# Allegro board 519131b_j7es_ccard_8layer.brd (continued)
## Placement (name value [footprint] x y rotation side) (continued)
J6  FAKRA II  [CONN-ST-FAKRA]  96.52 147.06 180 top
J7  FAKRA II  [CONN-ST-FAKRA]  54.99 146.42 180 top
J8  STX-4235-3/3  [CON_AV6_STX-4235-3-3_S_R_T_26]  6.99 129.02 270 top
J9  STX-4235-3/3  [CON_AV6_STX-4235-3-3_S_R_T_26]  6.99 109.97 270 top
J10  NP-HDR3  [HPH1-3-4025]  54.74 105.27 270 top
J11  2214BR-10G  [CON-2214BR-10G]  199.64 102.22 90 top
J12  STX-4235-3/3  [CON_AV6_STX-4235-3-3_S_R_T_26]  6.99 90.92 270 top
J13  Molex 34826-0124  [MOLEX-34826-0124]  14.86 53.33 270 top
J14  FAN  [CON2-200-250]  165.23 45.33 90 top
J15  MIPI-QSH-030  [QSH-030-01-F]  139.06 42.66 180 top
J16  D4S10E-40MA5-C  [CON_D4S10E]  108.58 6.59 0 top
J17  Phoenix_1868076  [PHOENIX_1868076]  182.25 9.01 0 top
J18  CON_MUSB_20_F  [CON_USB20_472720001_S_R_T_7]  133.84 6.22 0 top
J19  USBMINI_AB  [SAMTEC-MUSB]  16.31 8.75 0 top
J20  mini-pcie  [MOLEX-67910-0002]  89.28 125.97 180 bottom
J21  FX8-120P-SV1-91  [FX8-120P-SV1]  7.9 43.68 270 bottom
L1  NP  [L402-25]  69.6 149.6 270 top
L2  NP  [L402-25]  72.01 149.6 90 top
L3  72nH  [IND603-AISC-25X40]  39.37 138.04 270 top
L4  IHLP2020CZER2R2M01  [IND-IHLP2020]  107.57 137.78 0 top
L5  72nH  [IND603-AISC-25X40]  54.99 137.02 270 top
L6  330nH  [IND603-AISC-25X40]  26.92 134.23 0 top
L7  18nH  [IND603-AISC-25X40]  38.73 133.72 0 top
L8  3.3uH  [IND2-7030D]  169.8 133.72 90 top
L9  3.3uH  [IND2-7030D]  177.42 133.72 90 top
L10  3.3uH  [IND2-7030D]  185.04 133.72 90 top
L11  3.3uH  [IND2-7030D]  192.66 133.72 90 top
L12  62nH  [IND603-AISC-25X40]  48.9 133.59 90 top
L13  1.0uH  [IND0805-40X70]  30.35 133.21 180 top
L14  100nH  [IND603-AISC-25X40]  55.63 132.7 180 top
L15  100nH  [IND603-AISC-25X40]  38.73 131.94 0 top
L16  62nH  [IND603-AISC-25X40]  45.59 131.18 90 top
L17  39nH  [IND603-AISC-25X40]  49.4 130.93 0 top
L18  18nH  [IND603-AISC-25X40]  55.63 130.93 180 top
L19  1.5uH  [IND0805-40X70]  30.48 129.53 270 top
L20  160nH  [IND603-AISC-25X40]  39.37 129.28 270 top
L21  39nH  [IND603-AISC-25X40]  45.09 128.51 180 top
L22  160nH  [IND603-AISC-25X40]  54.99 128.26 270 top
L23  68nH  [IND603-AISC-25X40]  49.4 126.99 0 top
L24  72nH  [IND603-AISC-25X40]  38.61 124.7 0 top
L25  68nH  [IND603-AISC-25X40]  45.09 124.7 180 top
L26  72nH  [IND603-AISC-25X40]  55.75 123.69 180 top
L27  MPZ2012S102A  [L805-35X60]  36.2 118.86 90 top
L28  0.47uH  [IND1008_1-2]  70.99 113.02 180 top
L29  0.47uH  [IND1008_1-2]  82.17 113.02 0 top
L30  1uH  [IND1008_1-2]  69.09 108.96 180 top
L31  MPZ2012S102A  [L805-35X60]  31.75 104.26 90 top
L32  0.47uH  [IND1008_1-2]  124.84 102.99 90 top
L33  1uH  [IND1008_1-2]  138.05 102.99 90 top
L34  0.47uH  [IND1008_1-2]  70.99 99.81 180 top
L35  0.47uH  [IND1008_1-2]  82.17 99.81 0 top
L36  0.47uH  [IND1008_1-2]  124.84 91.81 270 top
L37  1uH  [IND1008_1-2]  138.05 91.81 270 top
L38  1uH  [IND1008_1-2]  128.91 89.91 270 top
L39  2.2uH  [IND_SRP1265A]  171.83 85.33 180 top
L40  120nH  [IND1608-27X40]  32.89 60.06 180 top
L41  AE2002  [CHOKE4-AE2002]  25.78 59.3 0 top
L42  120nH  [IND1608-27X40]  32.89 58.54 180 top
L43  5.6uH - IHLP5050FDER5R6M01  [IND-IHLP5050]  160.91 56 90 top
L44  XFL4012-471MEB, 470nH  [COIL-XLF4012]  151.13 31.99 90 top
L45  DFE252012PD-2R2M  [IND2520-40X80]  44.58 22.6 270 top
L46  3.3uH, 9A  [IND-DFEG10040]  174.62 21.07 180 top
L47  BLM18AG601SN1D  [L603-35X45]  23.5 20.82 180 top
L48  BLM18AG601SN1D  [L603-35X45]  30.91 20.82 0 top
L49  3.3uH, 13A  [IND-DFEH12060]  191.77 20.44 0 top
L50  XAL4020-222MEB  [COIL-XAL40]  152.15 9.39 180 top
L51  MPZ1608S102ATA00  [L603-35X45]  77.98 5.96 90 top
L52  MPZ1608S102ATA00  [L603-35X45]  28.07 5.96 90 top
L53  MPZ1608S102ATA00  [L603-35X45]  44.7 5.96 90 top
L54  MPZ1608S102ATA00  [L603-35X45]  61.34 5.96 90 top
L55  3.3uH  [IND2-7030D]  188.21 133.72 90 bottom
L56  3.3uH  [IND2-7030D]  180.47 133.72 90 bottom
L57  3.3uH  [IND2-7030D]  172.97 133.72 90 bottom
L58  3.3uH  [IND2-7030D]  165.48 133.72 90 bottom
L59  BLM18HE152SN1  [L603-35X45]  86.36 13.2 180 bottom
L60  BLM18HE152SN1  [L603-35X45]  69.72 13.2 180 bottom
L61  BLM18HE152SN1  [L603-35X45]  53.09 13.2 180 bottom
L62  BLM18HE152SN1  [L603-35X45]  36.45 13.2 180 bottom
L63  BLM18HE152SN1  [L603-35X45]  83.95 12.44 270 bottom
L64  BLM18HE152SN1  [L603-35X45]  67.31 12.44 270 bottom
L65  BLM18HE152SN1  [L603-35X45]  50.67 12.44 270 bottom
L66  BLM18HE152SN1  [L603-35X45]  34.04 12.44 270 bottom
L67  10uH  [IND2-LQH3N]  80.77 12.18 180 bottom
L68  10uH  [IND2-LQH3N]  64.14 12.18 180 bottom
L69  10uH  [IND2-LQH3N]  47.5 12.18 180 bottom
L70  10uH  [IND2-LQH3N]  30.86 12.18 180 bottom
L71  BLM18HE152SN1  [L603-35X45]  88.01 11.55 180 bottom
L72  BLM18HE152SN1  [L603-35X45]  71.37 11.55 180 bottom
L73  BLM18HE152SN1  [L603-35X45]  54.74 11.55 180 bottom
L74  BLM18HE152SN1  [L603-35X45]  38.1 11.55 180 bottom
L75  100uH  [IND-MSS7341]  80.9 6.09 270 bottom
L76  100uH  [IND-MSS7341]  64.26 6.09 270 bottom
L77  100uH  [IND-MSS7341]  47.62 6.09 270 bottom
L78  100uH  [IND-MSS7341]  30.99 6.09 270 bottom
M1  -  [MHP125-250]  5.59 146.8 0 top
M2  -  [MHP125-250]  196.72 146.8 0 top
M3  -  [MHP125-250]  198.75 6.34 0 top
M4  -  [MHP125-250]  5.21 5.83 0 top
M5  NT1R3000  [MHP098-175PIP]  88.9 149.85 180 bottom
M6  NT1R3000  [MHP098-175PIP]  64.64 149.85 180 bottom
M7  -  [MHP125-250]  8.13 68.95 90 bottom
M8  -  [MHP125-250]  8.13 18.4 90 bottom
NOREF  -  []  203.2 -9.41 90 top
NOREF#2  -  []  0 162.68 0 top
NOREF#3  -  [unnamed#2]  5.08 -4.33 0 top
NOREF#4  -  [unnamed#2]  198.12 157.6 0 top
NOREF#5  -  [unnamed#2]  198.12 -4.33 0 top
NOREF#6  -  [unnamed#2]  5.08 157.6 0 top
NOREF#7  -  []  203.2 0.75 90 top
NOREF#8  -  []  -587.38 -339.91 0 top
NOREF#9  -  []  54.48 112.51 0 top
NOREF#10  -  [unnamed#2]  5.08 157.6 180 bottom
NOREF#11  -  []  200.15 26.91 180 bottom
NOREF#12  -  [unnamed#2]  5.08 -4.33 180 bottom
NOREF#13  -  [unnamed#2]  198.12 -4.33 180 bottom
NOREF#14  -  [unnamed#2]  198.12 157.6 180 bottom
NOREF#15  -  []  187.32 22.85 180 bottom
P1  FAKRA II  [CONN-ST-FAKRA]  38.86 6.34 0 top
P2  FAKRA II  [CONN-ST-FAKRA]  55.5 6.34 0 top
P3  FAKRA II  [CONN-ST-FAKRA]  72.14 6.34 0 top
P4  FAKRA II  [CONN-ST-FAKRA]  88.77 6.34 0 top
P5  Micro SD, Reverse  [MOLEX-502774-0891]  9.02 80 90 bottom
PL1  PL0201  [R201PL]  55.24 112.26 270 top
Q1  BSS138PS  [SOT363-16X45]  128.27 129.4 0 top
Q2  BSS138PS  [SOT363-16X45]  198.63 76.95 0 top
Q3  BSZ068N06NSATMA1  [TSDSON8]  171.07 61.08 270 top
Q4  BSZ068N06NSATMA1  [TSDSON8]  170.43 56.63 90 top
Q5  BSZ068N06NSATMA1  [TSDSON8]  170.43 52.19 90 top
Q6  BSS138  [SOT23-28X44-GSD]  151.76 51.04 180 top
Q7  BSZ068N06NSATMA1  [TSDSON8]  171.07 47.74 270 top
Q8  BSS138PS  [SOT363-16X45]  91.95 22.98 0 top
Q9  SQJ422EP  [PWR-Q5A-SLPS319]  168.28 7.1 0 top
Q10  BSZ068N06NSATMA1  [TSDSON8]  185.04 86.35 0 bottom
Q11  BSZ068N06NSATMA1  [TSDSON8]  180.09 86.35 0 bottom
Q12  BSZ068N06NSATMA1  [TSDSON8]  185.04 81.52 0 bottom
Q13  BSZ068N06NSATMA1  [TSDSON8]  180.09 81.52 0 bottom
Q15  BSS138PS  [SOT363-16X45]  130.43 8.12 0 bottom
R1  4.75K  [R402-25]  106.81 150.1 270 top
R2  10K  [R402-25]  74.17 149.6 270 top
R3  2.2K  [R402-25]  78.99 148.83 0 top
R4  22  [R402-25]  81.03 148.83 0 top
R5  4.12K  [R402-25]  106.81 147.18 270 top
R6  240  [R402-25]  63.37 145.15 90 top
R7  680  [R402-25]  19.68 139.56 270 top
R8  NP-75  [R402-25]  22.61 139.56 90 top
R9  NP-75  [R402-25]  23.62 136.51 90 top
R10  680  [R402-25]  19.68 136.39 270 top
R11  NP-0  [R402-25]  20.83 136.39 270 top
R12  0  [R402-25]  102.87 136.26 90 top
R13  680  [R402-25]  19.68 133.21 270 top
R14  NP-75  [R402-25]  22.61 133.21 90 top
R15  22  [R402-25]  79.38 132.45 270 top
R16  22  [R402-25]  80.52 132.45 270 top
R17  10K  [R402-25]  141.22 131.94 270 top
R18  16.5K  [R402-25]  142.37 131.94 270 top
R19  3.48K  [R402-25]  143.51 131.94 90 top
R20  NP-75  [R402-25]  23.62 130.16 90 top
R21  10K  [R402-25]  78.61 130.16 270 top
R22  680  [R402-25]  19.68 130.04 270 top
R23  NP-0  [R402-25]  20.83 130.04 270 top
R24  120  [R402-25]  26.16 129.78 90 top
R25  10K  [R402-25]  102.36 128.89 180 top
R26  10K  [R402-25]  128.14 126.86 180 top
R27  NP  [R402-25]  32 126.61 90 top
R28  0  [R402-25]  70.99 126.23 270 top
R29  4.7K  [R402-25]  72.52 126.23 90 top
R30  0  [R402-25]  74.04 126.23 270 top
R31  4.7K  [R402-25]  75.18 126.23 90 top
R32  10K  [R402-25]  76.71 126.23 270 top
R33  4.99K  [R402-25]  153.16 126.23 270 top
R34  4.7K  [R402-25]  103.76 124.07 90 top
R35  10K  [R402-25]  105.03 124.07 270 top
R36  4.7K  [R402-25]  106.05 124.07 90 top
R37  10K  [R402-25]  107.06 124.07 90 top
R38  4.7K  [R402-25]  108.08 124.07 90 top
R39  100K  [R402-25]  145.16 123.69 180 top
R40  100K  [R402-25]  145.16 122.67 180 top
R41  100K  [R402-25]  86.23 121.66 270 top
R42  100K  [R402-25]  88.65 121.66 270 top
R43  80.6K  [R402-25]  145.16 121.66 180 top
R44  19.1K  [R402-25]  145.16 120.64 180 top
R45  680  [R402-25]  19.68 120.51 270 top
R46  NP-75  [R402-25]  22.61 120.51 90 top
R47  2K  [R402-25]  145.16 119.62 180 top
R48  100K  [R402-25]  151.76 118.61 90 top
R49  0  [R402-25]  152.78 118.61 90 top
R50  0  [R402-25]  153.8 118.61 90 top
R51  0  [R402-25]  145.16 117.59 0 top
R52  NP-75  [R402-25]  23.62 117.46 90 top
R53  680  [R402-25]  19.68 117.34 270 top
R54  NP-0  [R402-25]  20.83 117.34 270 top
R55  0  [R402-25]  151.76 116.07 90 top
R56  10K  [R402-25]  152.78 116.07 270 top
R57  680  [R402-25]  19.68 114.16 270 top
R58  NP-75  [R402-25]  22.61 114.16 90 top
R59  1M  [R402-25]  113.16 114.04 270 top
R60  9.53K  [R402-25]  99.44 113.53 0 top
R61  10K  [R402-25]  129.16 113.15 0 top
R62  2.2K  [R201-18P5X15]  125.09 113.02 90 top
R63  2.2K  [R201-18P5X15]  126.36 113.02 90 top
R64  10K  [R402-25]  53.59 112.13 90 top
R65  NP-75  [R402-25]  23.62 111.11 90 top
R66  680  [R402-25]  19.68 110.99 270 top
R67  NP-0  [R402-25]  20.83 110.99 270 top
R68  10K  [R402-25]  36.7 109.59 180 top
R69  3.32K  [R402-25]  186.56 109.08 270 top
R70  47K  [R402-25]  187.83 109.08 270 top
R71  9.09K  [R402-25]  104.01 106.92 180 top
R72  10K  [RES0402_0-5]  128.02 106.92 90 top
R73  10K  [R201-18P5X15]  59.44 106.42 270 top
R74  10K  [R402-25]  104.01 105.78 0 top
R75  10K  [R402-25]  104.01 104.64 180 top
R76  680  [R402-25]  19.68 101.46 270 top
R77  NP-75  [R402-25]  22.61 101.46 90 top
R78  NP-75  [R402-25]  23.62 98.41 90 top
R79  680  [R402-25]  19.68 98.29 270 top
R80  NP-0  [R402-25]  20.83 98.29 270 top
R81  44.2  [R201-18P5X15]  49.15 97.27 270 top
R82  44.2  [R201-18P5X15]  49.91 97.27 270 top
R83  0  [RES0402_0-5]  153.8 95.87 180 top
R84  10K  [R402-25]  167.7 95.7 0 top
R85  44.2  [R201-18P5X15]  39.12 95.49 270 top
R86  44.2  [R201-18P5X15]  39.88 95.49 270 top
R87  44.2  [R201-18P5X15]  40.64 95.49 270 top
R88  44.2  [R201-18P5X15]  41.4 95.49 270 top
R89  44.2  [R201-18P5X15]  42.16 95.49 270 top
R90  44.2  [R201-18P5X15]  42.93 95.49 270 top
R91  44.2  [R201-18P5X15]  43.69 95.49 270 top
R92  44.2  [R201-18P5X15]  44.45 95.49 270 top
R93  44.2  [R201-18P5X15]  47.37 95.49 90 top
R94  44.2  [R201-18P5X15]  48.26 95.49 90 top
R95  10K  [R402-25]  112.78 95.49 0 top
R96  680  [R402-25]  19.68 95.11 270 top
R97  NP-75  [R402-25]  22.61 95.11 90 top
R98  240  [RES0402_0-5]  158.37 94.73 270 top
R99  240  [RES0402_0-5]  156.84 94.22 180 top
R100  1K  [R201-18P5X15]  48.26 93.33 270 top
R101  NP-75  [R402-25]  23.62 92.06 90 top
R102  680  [R402-25]  19.68 91.94 270 top
R103  NP-0  [R402-25]  20.83 91.94 270 top
R104  1.0  [R1206-40X70]  180.97 90.41 0 top
R105  0  [RES0402_0-5]  136.78 89.02 180 top
R106  0  [R402-25]  191.13 88.64 270 top
R107  42.2K  [R402-25]  193.42 88.64 270 top
R108  10K  [R402-25]  196.09 88.64 270 top
R109  44.2  [R201-18P5X15]  64.39 88 180 top
R110  44.2  [R201-18P5X15]  64.39 87.24 180 top
R111  NP  [R402-25]  197.61 87.11 0 top
R112  1K  [R201-6P6SPC]  14.86 86.6 0 top
R113  10K  [R402-25]  3.94 86.48 90 top
R114  1.5K  [R402-25]  5.21 86.48 90 top
R115  1K  [R201-18P5X15]  64.39 86.48 180 top
R116  44.2  [R201-18P5X15]  64.39 85.71 180 top
R117  8.45K  [R402-25]  197.1 83.56 270 top
R118  2.2K  [R201-18P5X15]  38.23 83.43 180 top
R119  0  [R402-25]  115.44 83.43 0 top
R120  44.2  [R201-18P5X15]  69.98 83.3 180 top
R121  2.2K  [R201-18P5X15]  38.23 82.67 180 top
R122  44.2  [R201-18P5X15]  70.48 81.9 180 top
R123  20K  [R402-25]  197.74 81.65 180 top
R124  34.8K  [R402-25]  197.74 80.51 0 top
R125  200  [R402-25]  199.9 80.51 0 top
R126  2.2K  [R201-18P5X15]  143 78.98 90 top
R127  0  [R402-25]  194.44 78.98 180 top
R128  1K  [R201-18P5X15]  66.17 78.22 90 top
R129  NP-2K  [R402-25]  195.45 77.84 180 top
R130  44.2  [R201-18P5X15]  69.09 76.95 180 top
R131  2.2K  [R201-18P5X15]  143 76.95 270 top
R132  10K  [RES0402_0-5]  120.78 76.7 90 top
R133  5.49K  [R402-25]  195.45 76.7 0 top
R134  44.2  [R201-18P5X15]  69.09 76.06 180 top
R135  0  [R402-25]  146.3 68.95 270 top
R136  10K  [R201-18P5X15]  152.53 75.17 270 top
R137  10K  [R402-25]  8.38 74.28 180 top
R138  63.4K  [R402-25]  10.54 74.28 180 top
R139  10K  [R402-25]  5.21 73.78 90 top
R140  0  [R402-25]  6.48 73.78 270 top
R141  0  [R402-25]  78.87 73.65 90 top
R142  10K  [R402-25]  30.99 72.63 180 top
R143  0  [R402-25]  72.01 70.98 90 top
R144  11K  [R402-25]  82.35 68.39 270 top
R145  3.01K  [R402-25]  80.14 67.99 180 top
R146  0  [R402-25]  75.69 67.55 0 top
R147  0  [R402-25]  72.52 67.45 180 top
R148  100K  [R402-25]  20.45 65.65 180 top
R149  10K  [R402-25]  79.38 65.52 180 top
R150  0  [R402-25]  169.54 65.39 270 top
R151  0  [R402-25]  81.89 64.4 180 top
R152  NP-0  [R402-25]  34.92 62.85 180 top
R153  1.82K  [R603-35X45]  195.07 61.46 0 top
R154  1.5K  [R402-25]  45.72 61.2 270 top
R155  10K  [R402-25]  80.26 61.2 90 top
R156  100  [R402-25]  81.41 61.2 270 top
R157  100  [R402-25]  83.19 61.2 270 top
R158  10K  [R402-25]  84.2 61.2 90 top
R159  100  [R402-25]  185.67 60.95 90 top
R160  100  [R402-25]  186.94 60.95 90 top
R161  1K  [R402-25]  18.41 60.7 90 top
R162  27  [R402-25]  30.86 60.57 90 top
R163  2.2K  [R201-18P5X15]  70.23 60.44 0 top
R164  10K  [R402-25]  188.47 59.81 270 top
R165  NP-0  [R402-25]  46.23 59.55 0 top
R166  2.2K  [R201-18P5X15]  70.23 59.55 0 top
R167  100K  [R402-25]  194.44 59.3 90 top
R168  10  [R402-25]  195.71 59.3 270 top
R169  10K  [R201-18P5X15]  80.52 58.92 180 top
R170  1K  [R402-25]  18.41 58.03 270 top
R171  27  [R402-25]  30.86 58.03 270 top
R172  3.01  [R402-25]  175.51 57.9 180 top
R173  0  [R402-25]  175.51 56.63 0 top
R174  0  [R402-25]  85.47 55.87 270 top
R175  5.36K  [R603-35X45]  196.47 55.36 180 top
R176  NP-0  [R402-25]  35.05 53.84 180 top
R177  2.49K  [R402-25]  41.15 53.46 90 top
R178  2.49K  [R402-25]  42.16 53.46 90 top
R179  NP-2.49K  [R402-25]  43.18 53.46 90 top
R180  0.008-PRL1632-R008-F-T1  [R0612]  175.13 53.33 270 top
R181  3.16K  [R603-35X45]  194.69 52.95 90 top
R182  36.5K  [R402-25]  196.6 51.17 0 top
R183  10K  [RES0402_0-5]  91.19 50.92 0 top
R184  0  [R402-25]  198.88 50.92 180 top
R185  0  [R402-25]  80.39 49.65 270 top
R186  NP-0  [R402-25]  81.66 49.65 270 top
R187  10K  [R201-18P5X15]  77.6 49.52 90 top
R188  10K  [R201-18P5X15]  78.87 49.52 90 top
R189  93.1K  [R402-25]  198.5 48.63 90 top
R190  100K  [R402-25]  82.04 48.12 0 top
R191  10K  [R201-18P5X15]  151.76 48 90 top
R192  0  [R402-25]  76.1 47.74 0 top
R193  NP  [R402-25]  196.47 46.98 180 top
R194  10K  [R201-18P5X15]  82.17 46.85 0 top
R195  10K  [R201-18P5X15]  81.28 46.09 0 top
R196  10K  [R402-25]  76.58 45.96 0 top
R197  22E  [R402-25]  83.31 45.84 0 top
R198  10  [R402-25]  193.55 45.84 90 top
R199  10  [R402-25]  194.82 45.84 90 top
R200  10K  [R402-25]  85.22 44.82 90 top
R201  10K  [R402-25]  76.58 44.59 0 top
R202  3.01  [R402-25]  169.54 43.93 270 top
R203  10K  [R402-25]  83.31 43.8 180 top
R204  10K  [R402-25]  77.72 42.28 90 top
R205  10K  [R402-25]  79.76 42.28 90 top
R206  10K  [R402-25]  80.77 42.28 90 top
R207  10K  [R402-25]  81.79 42.28 90 top
R208  10K  [R402-25]  82.8 42.28 90 top
R209  1K  [R201-18P5X15]  57.78 41.26 0 top
R210  0  [R402-25]  11.05 40.5 270 top
R211  2.2K  [R201-18P5X15]  5.21 37.58 180 top
R212  22  [R402-25]  46.35 36.95 0 top
R213  2.2K  [R201-18P5X15]  5.21 36.69 180 top
R214  10K  [R402-25]  46.35 35.93 0 top
R215  0  [R402-25]  5.21 35.68 0 top
R216  10K  [R402-25]  46.35 34.91 0 top
R217  22  [R402-25]  38.35 34.79 0 top
R218  10K  [R402-25]  38.35 33.77 180 top
R219  0  [R402-25]  5.21 33.26 0 top
R220  44.2  [R201-18P5X15]  8.26 33.14 270 top
R221  10K  [R402-25]  46.35 31.1 180 top
R222  10K  [R402-25]  10.79 30.6 270 top
R223  22  [R402-25]  46.35 28.82 0 top
R224  475K  [R402-25]  150.37 28.82 180 top
R225  0  [R402-25]  10.79 28.31 90 top
R226  22  [R402-25]  38.35 27.68 0 top
R227  10K  [R402-25]  46.35 27.42 0 top
R228  2.2K  [R201-18P5X15]  104.78 27.29 180 top
R229  200K  [R402-25]  152.4 26.91 270 top
R230  160K  [R402-25]  153.67 26.91 90 top
R231  10K  [R402-25]  38.35 26.66 180 top
R232  2.2K  [R402-25]  19.35 26.43 180 top
R233  2.2K  [R201-18P5X15]  104.78 26.28 180 top
R234  10K  [R402-25]  91.44 25.39 0 top
R235  12K  [R402-25]  26.29 24.63 90 top
R236  1K  [R402-25]  32.69 24.5 180 top
R237  240  [R402-25]  13.59 23.36 90 top
R238  1K  [R402-25]  14.99 23.36 270 top
R239  1K  [R402-25]  16.89 21.45 180 top
R240  100K  [R402-25]  128.78 20.1 180 top
R241  100K  [R402-25]  130.81 20.1 180 top
R242  10K  [R201-18P5X15]  92.46 19.42 270 top
R243  475K  [R402-25]  37.21 19.29 180 top
R244  150K  [R402-25]  39.75 19.29 180 top
R245  475K  [R402-25]  43.94 18.79 0 top
R246  41.2K  [R402-25]  104.01 16.79 90 top
R247  10K  [R402-25]  163.07 16.75 180 top
R248  41.2K  [R402-25]  111.63 16.28 90 top
R249  30.9K  [R402-25]  112.78 16.28 270 top
R250  10K  [R402-25]  93.09 14.98 270 top
R251  4.7K  [R402-25]  94.36 14.98 270 top
R252  1.87K  [R603-35X45]  95.63 14.98 270 top
R253  4.7K  [R402-25]  96.9 14.98 270 top
R254  3.32K  [R402-25]  162.56 14.21 270 top
R255  0  [R402-25]  21.26 11.04 180 top
R256  10K  [R402-25]  119.51 10.53 0 top
R257  10K  [R402-25]  162.56 9.51 90 top
R258  0  [R402-25]  155.96 6.85 90 top
R259  95.3K  [R402-25]  161.29 6.85 270 top
R260  1K  [R402-25]  163.96 5.7 90 top
R261  49.9  [R402-25]  160.78 5.2 180 top
R262  3.01  [R402-25]  106.05 135.88 270 bottom
R263  3.01  [R402-25]  104.9 135.88 270 bottom
R264  10K  [R402-25]  131.95 134.74 270 bottom
R265  10K  [R402-25]  130.94 134.74 270 bottom
R266  10K  [R402-25]  131.44 131.18 0 bottom
R267  3.01  [R402-25]  105.41 131.18 0 bottom
R268  47  [R402-25]  114.05 130.42 270 bottom
R269  158K  [R402-25]  135.64 129.28 90 bottom
R270  10K  [R402-25]  111.89 129.28 90 bottom
R271  10K  [R402-25]  110.74 129.28 90 bottom
R272  40.2K  [R402-25]  113.54 128.77 180 bottom
R273  NP-4.7K  [R402-25]  116.2 119.62 270 bottom
R274  NP-4.7K  [R402-25]  112.9 119.62 270 bottom
R275  4.7K  [R402-25]  102.11 115.81 180 bottom
R276  NP-4.7K  [R402-25]  102.11 114.8 180 bottom
R277  10K  [RES0402_0-5]  83.19 112.89 180 bottom
R278  4.7K  [R402-25]  110.74 112 270 bottom
R279  4.7K  [R402-25]  109.22 112 270 bottom
R280  10K  [R402-25]  39.88 111.62 0 bottom
R281  0  [R402-25]  197.23 104.26 180 bottom
R282  2.2K  [R201-18P5X15]  194.69 104.26 0 bottom
R283  NP-0  [RES0402_0-5]  82.93 104.13 0 bottom
R284  10K  [RES0402_0-5]  128.02 103.62 90 bottom
R285  10K  [RES0402_0-5]  57.4 103.49 0 bottom
R286  0  [RES0402_0-5]  57.4 102.22 180 bottom
R287  0  [R402-25]  197.23 101.72 180 bottom
R288  2.2K  [R201-18P5X15]  194.69 101.72 0 bottom
R289  10K  [R402-25]  63.88 100.83 270 bottom
R290  10K  [RES0402_0-5]  135.51 99.68 90 bottom
R291  0  [RES0402_0-5]  127.38 98.41 90 bottom
R292  2.2K  [R402-25]  195.96 96.76 0 bottom
R293  10K  [R402-25]  143.89 96.13 90 bottom
R294  0  [RES0402_0-5]  134.75 95.24 90 bottom
R295  100  [R402-25]  195.96 94.22 180 bottom
R296  0  [R402-25]  195.96 91.81 0 bottom
R297  47K  [R402-25]  152.27 90.03 180 bottom
R298  47K  [R402-25]  149.35 90.03 180 bottom
R299  0  [R402-25]  192.41 88.64 90 bottom
R300  NP  [R402-25]  191.26 88.64 90 bottom
R301  47K  [R402-25]  146.43 88.25 0 bottom
R302  22E  [R402-25]  144.27 88.25 0 bottom
R303  0E  [RES0402_0-5]  71.75 88.25 270 bottom
R304  NP  [RES0402_0-5]  70.61 88.25 270 bottom
R305  NP  [RES0402_0-5]  69.47 88.25 270 bottom
R306  0E  [RES0402_0-5]  68.33 88.25 270 bottom
R307  3.32K  [R402-25]  33.91 87.49 180 bottom
R308  10K  [R402-25]  195.83 87.37 90 bottom
R309  3.3  [R402-25]  187.45 87.37 90 bottom
R310  0  [R402-25]  182.5 87.37 270 bottom
R311  47K  [R402-25]  152.27 87.37 180 bottom
R312  47K  [R402-25]  148.34 87.37 0 bottom
R313  1K  [R402-25]  150.11 86.35 90 bottom
R314  47K  [R402-25]  148.34 85.33 180 bottom
R315  10K  [R402-25]  196.47 84.95 0 bottom
R316  10K  [R201-18P5X15]  92.46 84.95 90 bottom
R317  0  [R402-25]  146.94 84.7 270 bottom
R318  47K  [R402-25]  145.92 84.7 90 bottom
R319  36  [R201-18P5X15]  22.99 84.57 180 bottom
R320  47K  [R201-6P6SPC]  21.08 84.57 0 bottom
R321  10K  [R402-25]  22.99 83.68 0 bottom
R322  36  [R201-18P5X15]  21.08 83.68 180 bottom
R323  100K  [R402-25]  196.6 83.17 0 bottom
R324  47K  [R402-25]  152.15 83.05 180 bottom
R325  47K  [R402-25]  149.48 83.05 180 bottom
R326  0  [R402-25]  187.45 82.54 270 bottom
R327  0  [R402-25]  182.5 82.54 90 bottom
R328  49.9  [R402-25]  97.18 80.51 45 bottom
R329  47K  [R402-25]  151.26 80.25 0 bottom
R330  47K  [R402-25]  149.22 80.25 180 bottom
R331  10K  [R201-18P5X15]  111.07 80.15 90 bottom
R332  3.01K  [R201-18P5X15]  105.16 80.13 0 bottom
R333  3.01K  [R201-18P5X15]  101.22 80.13 0 bottom
R334  3.01K  [R201-18P5X15]  95.58 80.13 180 bottom
R335  36  [R201-18P5X15]  22.86 79.87 180 bottom
R336  47K  [R201-6P6SPC]  21.08 79.87 0 bottom
R337  500E_0.1%  [R402-25]  103.58 79.75 135 bottom
R338  49.9  [R402-25]  97.97 79.75 45 bottom
R339  47K  [R201-6P6SPC]  22.86 79.11 0 bottom
R340  36  [R201-18P5X15]  21.08 79.11 180 bottom
R341  3.01K  [R201-18P5X15]  100.18 78.93 270 bottom
R342  100K  [R402-25]  198.63 77.84 270 bottom
R343  500E_0.1%  [R402-25]  112.52 77.59 0 bottom
R344  36  [R201-18P5X15]  22.73 75.3 180 bottom
R345  47K  [R201-6P6SPC]  21.08 75.3 0 bottom
R346  47K  [R201-6P6SPC]  22.73 74.54 0 bottom
R347  36  [R201-18P5X15]  21.08 74.54 180 bottom
R348  10K  [R201-18P5X15]  106.4 72.43 90 bottom
R349  NP-10K  [R402-25]  135.71 71.74 90 bottom
R350  36  [R201-18P5X15]  22.73 70.86 180 bottom
R351  47K  [R201-6P6SPC]  22.73 70.09 0 bottom
R352  10K  [R402-25]  135.71 69.84 90 bottom
R353  10K  [R402-25]  117.6 68.7 90 bottom
R354  NP  [R402-25]  13.59 66.54 90 bottom
R355  NP  [R402-25]  12.45 66.54 90 bottom
R356  240  [R201-18P5X15]  109.98 65.34 315 bottom
R357  3.32K  [R402-25]  39.37 64.51 180 bottom
R358  500E_0.1%  [R402-25]  99.19 64.38 90 bottom
R359  NP-10K  [R402-25]  133.96 64.3 90 bottom
R360  3.01K  [R201-18P5X15]  104.39 64.12 0 bottom
R361  500E_0.1%  [R402-25]  101.6 63.74 270 bottom
R362  3.32K  [R402-25]  45.34 63.49 270 bottom
R363  240  [R402-25]  44.07 63.49 270 bottom
R364  0  [R402-25]  40.26 63.36 180 bottom
R365  10K  [R402-25]  133.96 62.52 90 bottom
R366  500E_0.1%  [R402-25]  99.19 62.46 270 bottom
R367  NP  [R402-25]  2.92 61.46 180 bottom
R368  3.32K  [R402-25]  38.99 60.95 270 bottom
R369  3.32K  [R402-25]  37.85 60.95 270 bottom
R370  NP  [R402-25]  2.92 59.81 0 bottom
R371  100  [R402-25]  60.83 59.68 90 bottom
R372  100  [R402-25]  57.02 59.68 90 bottom
R373  240  [R201-18P5X15]  128.02 58.92 90 bottom
R374  240  [R201-18P5X15]  126.87 58.92 90 bottom
R375  NP  [R402-25]  2.92 58.79 0 bottom
R376  0  [R402-25]  2.92 57.27 0 bottom
R377  10K  [R402-25]  60.83 56.89 90 bottom
R378  22  [R402-25]  93.23 56.79 180 bottom
R379  0  [R402-25]  16.38 56.5 0 bottom
R380  0  [R402-25]  2.92 56.25 0 bottom
R381  10K  [RES0402_0-5]  78.87 55.49 180 bottom
R382  0  [R402-25]  16.38 55.36 0 bottom
R383  22  [R402-25]  93.23 55.35 180 bottom
R384  62  [R1206-40X70]  20.57 54.47 180 bottom
R385  10K  [R201-18P5X15]  80.9 54.22 270 bottom
R386  100  [R402-25]  60.83 54.09 90 bottom
R387  62  [R1206-40X70]  20.57 52.19 0 bottom
R388  100  [R402-25]  32.77 51.93 90 bottom
R389  100  [R402-25]  28.96 51.93 90 bottom
R390  100  [R402-25]  26.42 51.93 270 bottom
R391  100K  [R402-25]  25.15 51.93 90 bottom
R392  100  [R402-25]  23.88 51.93 270 bottom
R393  4.7K  [R402-25]  149.1 51.55 90 bottom
R394  10K  [R402-25]  26.42 49.27 90 bottom
R395  1K  [R201-18P5X15]  68.96 48.76 90 bottom
R396  1K  [R201-18P5X15]  67.69 48.76 90 bottom
R397  1K  [R201-18P5X15]  66.42 48.76 90 bottom
R398  1K  [R201-18P5X15]  65.15 48.76 90 bottom
R399  1K  [R201-18P5X15]  63.88 48.76 90 bottom
R400  1K  [R201-18P5X15]  62.61 48.76 90 bottom
R401  1K  [R201-18P5X15]  61.34 48.76 90 bottom
R402  1K  [R201-18P5X15]  60.07 48.76 90 bottom
R403  100  [R402-25]  34.04 48.76 270 bottom
R404  62  [R1206-40X70]  20.57 48.5 180 bottom
R405  10K  [R402-25]  34.04 46.6 90 bottom
R406  33.2K  [R402-25]  26.42 46.6 90 bottom
R407  100  [R402-25]  25.15 46.6 90 bottom
R408  3.32K  [R402-25]  23.88 46.6 90 bottom
R409  62  [R1206-40X70]  20.57 46.22 0 bottom
R410  4.7K  [R402-25]  146.81 45.84 90 bottom
R411  0  [R402-25]  145.8 45.84 90 bottom
R412  4.7K  [R402-25]  144.15 45.84 90 bottom
R413  0  [R402-25]  142.88 45.84 90 bottom
R414  4.7K  [R402-25]  141.6 45.84 90 bottom
R415  4.7K  [R402-25]  140.34 45.84 90 bottom
R416  10K  [R201-18P5X15]  68.96 41.14 90 bottom
R417  10K  [R201-18P5X15]  67.69 41.14 90 bottom
R418  10K  [R201-18P5X15]  66.42 41.14 90 bottom
R419  10K  [R201-18P5X15]  65.15 41.14 90 bottom
R420  10K  [R201-18P5X15]  63.88 41.14 90 bottom
R421  10K  [R201-18P5X15]  62.61 41.14 90 bottom
R422  10K  [R201-18P5X15]  61.34 41.14 90 bottom
R423  10K  [R201-18P5X15]  60.07 41.14 90 bottom
R424  100  [R402-25]  143.76 40.12 90 bottom
R425  4.7K  [R402-25]  145.03 39.49 90 bottom
R426  10K  [R402-25]  57.66 27.8 180 bottom
R427  10K  [R402-25]  57.66 26.79 180 bottom
R428  NP  [R402-25]  74.17 26.15 180 bottom
R429  4.7K  [R402-25]  57.66 25.77 0 bottom
R430  10K  [R402-25]  74.17 25.14 0 bottom
R431  10K  [R402-25]  57.66 24.75 180 bottom
R432  1K  [R402-25]  17.2 23.99 270 bottom
R433  10K  [R402-25]  57.66 23.74 180 bottom
R434  0  [R402-25]  101.98 23.48 0 bottom
R435  0  [R402-25]  99.69 23.48 180 bottom
R436  NP  [R402-25]  74.17 22.09 0 bottom
R437  0  [R402-25]  115.34 21.95 0 bottom
R438  4.7K  [R402-25]  92.84 21.83 270 bottom
R439  10K  [R402-25]  91.57 21.83 90 bottom
R440  13.3K  [R402-25]  74.17 21.07 180 bottom
R441  49.9  [R402-25]  56.77 17.9 180 bottom
R442  10K  [R402-25]  105.16 16.79 270 bottom
R443  30.9K  [R402-25]  104.01 16.79 270 bottom
R444  49.9  [R402-25]  72.77 16.75 0 bottom
R445  100  [R402-25]  64.77 16.63 180 bottom
R446  61.9K  [R402-25]  112.78 16.28 270 bottom
R447  30.1K  [R402-25]  111.63 16.28 90 bottom
R448  4.7K  [R402-25]  106.53 15.98 90 bottom
R449  49.9  [R402-25]  56.77 15.74 180 bottom
R450  4.02K  [R402-25]  80.77 14.47 180 bottom
R451  49.9  [R402-25]  72.77 14.59 0 bottom
R452  4.02K  [R402-25]  47.5 14.47 180 bottom
R453  4.02K  [R402-25]  30.86 14.47 180 bottom
R454  4.02K  [R402-25]  64.14 14.47 180 bottom
R455  0  [R402-25]  106.3 14.34 180 bottom
R456  0  [R402-25]  133.62 13.23 90 bottom
R457  0  [R402-25]  132.48 13.23 90 bottom
R458  100K  [R402-25]  128.4 7.48 90 bottom
R459  2K  [R402-25]  85.6 6.09 270 bottom
R460  2K  [R402-25]  68.83 6.09 270 bottom
R461  2K  [R402-25]  52.2 6.09 270 bottom
R462  2K  [R402-25]  35.69 6.09 270 bottom
R463  10K  [RES0402_0-5]  147.57 68.95 90 top
R464  100K  [R402-25]  131.06 5.96 0 bottom
R465  100K  [R402-25]  132.46 8.12 270 bottom
RJ1  0.A  [JMP402-25]  102.36 126.35 0 top
RJ2  0  [JMP402-25]  153.16 123.31 270 top
RJ3  10K  [JMP402-25]  137.79 87.75 180 top
RJ4  10K.A  [JMP402-25]  63.63 81.4 270 top
RJ5  10K.A  [JMP402-25]  64.9 81.4 270 top
RJ6  10K.A  [JMP402-25]  66.17 81.4 270 top
RJ7  10K.A  [JMP402-25]  67.44 81.4 270 top
RJ8  10K.A  [JMP402-25]  64.77 57.27 270 top
RJ9  10K.A  [JMP402-25]  66.04 57.27 270 top
RJ10  10K.A  [JMP402-25]  67.31 57.27 270 top
RJ11  10K.A  [JMP402-25]  68.58 57.27 270 top
RJ12  10K.A  [JMP402-25]  69.85 57.27 270 top
RJ13  10K.A  [JMP402-25]  71.12 57.27 270 top
RJ14  0.A  [JMP402-25]  69.85 53.46 270 top
RJ15  0.A  [JMP402-25]  71.12 53.46 270 top
RJ16  0  [JMP402-25]  82.8 52.57 0 top
RJ17  0.B  [JMP402-25]  91.19 49.39 0 top
RJ18  3.32K.A  [JMP402-25]  28.96 48.38 90 bottom
RJ19  0.A  [JMP402-25]  144.78 42.03 90 bottom
RJ20  NP  [JMP402-25]  13.34 33.26 90 bottom
SW1  SW DIP-2  [SW2-30X50-TDA]  199.64 69.59 0 top
SW2  TDA08H0SB1R  [SW8-30X50]  64.52 44.95 0 top
SW3  PB_SW  [SW4-7914G]  6.99 28.31 180 top
TP1  TP  [TP20]  83.82 149.21 180 top
TP2  TP  [TP-30RD13]  108.2 145.15 180 top
TP3  TP  [TP-30RD13]  116.71 139.31 0 top
TP4  TP  [TP-30RD13]  70.87 132.96 180 top
TP5  TP  [TP-30RD13]  97.66 128.39 270 top
TP6  TP  [TP-20RD10]  100.71 127.88 0 top
TP7  TP  [TP-30RD13]  105.41 127.62 0 top
TP8  TP  [TP-30RD13]  131.83 126.48 0 top
TP9  TP  [TP-30RD13]  40.01 120.13 90 top
TP10  TP  [TP-30RD13]  113.92 120.13 270 top
TP11  TP  [TP-30RD13]  115.32 120.13 270 top
TP12  TP  [TP-30RD13]  146.81 119.12 0 top
TP13  TP_VIA_MEM0  [TP-18RD8]  78.13 109.67 180 bottom
TP14  TP_VIA_MEM0  [TP-18RD8]  78.36 111.62 180 bottom
TP15  TP  [TP-30RD13]  127.64 113.15 180 top
TP16  TP_VIA_MEM0  [TP-18RD8]  59.44 108.57 0 top
TP17  TP_VIA_MEM0  [TP-18RD8]  59.44 107.56 0 top
TP18  TP  [TP-30RD13]  33.66 106.42 270 top
TP19  TP_VIA_MEM0  [TP-18RD8]  59.44 104 0 top
TP20  TP  [TP-20RD10]  56.9 101.34 270 top
TP21  TP  [TP-20RD10]  47.37 96.89 180 top
TP22  TP  [TP-20RD10]  48.26 96.89 180 top
TP23  TP_VIA_MEM0  [TP-18RD8]  143.89 94.73 0 top
TP24  TP  [TP-20RD10]  39.88 94.22 180 top
TP25  TP  [TP-20RD10]  41.4 94.22 180 top
TP26  TP  [TP-20RD10]  42.93 94.22 270 top
TP27  TP  [TP-20RD10]  44.45 94.22 270 top
TP28  TP  [TP-20RD10]  39.88 92.95 180 top
TP29  TP  [TP-20RD10]  41.4 92.95 180 top
TP30  TP  [TP-20RD10]  42.93 92.95 270 top
TP31  TP  [TP-20RD10]  44.45 92.95 270 top
TP32  TP_VIA_MEM0  [TP-18RD8]  72.14 91.3 270 top
TP33  TP  [TP-30RD13]  200.41 90.29 270 top
TP34  TP_VIA_MEM0  [TP-18RD8]  126.62 89.14 0 top
TP35  TP_VIA_MEM0  [TP-18RD8]  141.6 87.62 0 top
TP36  TP_VIA_MEM0  [TP-18RD8]  69.47 87.11 270 top
TP37  TP_VIA_MEM0  [TP-18RD8]  70.61 87.11 180 top
TP38  TP_VIA_MEM0  [TP-18RD8]  91.57 85.71 0 top
TP39  -  [TP40_SMD]  70.23 79.87 0 top
TP40  TP_VIA_MEM0  [TP-18RD8]  147.57 67.05 0 top
TP41  TP  [TP-30RD13]  14.1 76.06 90 top
TP42  TP  [TP-30RD13]  3.3 74.41 90 top
TP43  TP  [TP-20RD10]  195.96 68.82 0 top
TP44  TP  [TP-30RD13]  171.58 65.52 90 top
TP45  TP  [TP-30RD13]  194.31 63.24 180 top
TP46  TP  [TP-20RD10]  68.58 62.98 0 top
TP47  TP  [TP-20RD10]  69.85 62.98 0 top
TP48  TP  [TP-20RD10]  71.12 62.98 0 top
TP49  TP_VIA_MEM0  [TP-18RD8]  82.3 61.71 0 top
TP50  TP_VIA_MEM0  [TP-18RD8]  85.09 61.71 0 top
TP51  TP_VIA_MEM0  [TP-18RD8]  81.53 58.92 0 top
TP52  SMT-TP  [TP1-70X135]  198.88 58.54 180 top
TP53  TP  [TP-30RD13]  183.51 58.28 180 top
TP54  TP_VIA_MEM0  [TP-18RD8]  108.48 55.64 0 top
TP55  TP_VIA_MEM0  [TP-18RD8]  80.26 55.49 0 top
TP56  TP  [TP-30RD13]  34.92 55.36 90 top
TP57  -  [TP40_SMD]  103 52.44 0 top
TP58  TP  [TP-20RD10]  89.41 49.39 0 top
TP59  TP  [TP-20RD10]  199.52 46.85 0 top
TP60  TP  [TP-30RD13]  197.1 43.3 90 top
TP61  TP  [TP-30RD13]  14.61 40.5 90 top
TP62  TP  [TP-30RD13]  153.8 35.04 90 top
TP63  TP  [TP-30RD13]  2.67 34.91 90 top
TP64  TP  [TP-30RD13]  152.27 28.82 90 top
TP65  TP  [TP-30RD13]  200.91 20.69 180 top
TP66  TP_VIA_MEM0  [TP-18RD8]  92.46 20.56 0 top
TP67  TP  [TP-30RD13]  76.45 18.28 180 top
TP68  TP  [TP-30RD13]  35.43 18.02 90 top
TP69  NP  [TP20]  94.36 16.5 180 top
TP70  TP  [TP-30RD13]  122.3 14.85 0 top
TP71  TP  [TP-20RD10]  163.58 14.72 0 top
TP72  TP  [TP-30RD13]  122.56 8.63 90 top
TP73  TP  [TP-30RD13]  149.61 6.21 90 top
TP74  TP  [TP-30RD13]  100.08 5.32 0 top
TP75  -  [TP40_SMD]  108.71 3.42 180 bottom
TP76  TP_VIA_MEM0  [TP-18RD8]  65.41 15.36 270 top
TP77  TP_VIA_MEM0  [TP-18RD8]  64.14 15.36 270 top
TP78  SMT-TP  [TP1-70X135]  47.88 81.02 0 top
TP79  SMT-TP  [TP1-70X135]  92.33 31.74 0 top
TP80  SMT-TP  [TP1-70X135]  112.01 106.67 0 top
TP81  SMT-TP  [TP1-70X135]  28.45 117.97 180 bottom
TP82  SMT-TP  [TP1-70X135]  46.48 45.07 180 bottom
TP83  SMT-TP  [TP1-70X135]  165.35 35.93 180 bottom
TP84  SMT-TP  [TP1-70X135]  158.37 107.94 180 bottom
U1  TPS74701  [DRC10-11X33]  111.89 148.2 90 top
U2  -  [NEO-M8U]  76.79 141.11 180 top
U3  TPD1E10B09  [DPY]  18.41 139.56 270 top
U4  TPD1E10B09  [DPY]  18.41 136.39 90 top
U5  TPD1E10B09  [DPY]  18.41 133.21 270 top
U6  LP5912Q1.1DRVTQ1  [DRV6-12X30]  98.42 132.45 0 top
U7  TPD3S716-Q1  [SSOP-16]  133.35 131.94 180 top
U8  LM53603-Q1  [PWP16-14X70-PAD]  108.46 131.56 270 top
U9  TPD1E10B09  [DPY]  18.41 130.04 90 top
U10  SN74LVC1G08DCKR-Q1  [DCK-5]  76.71 129.66 0 top
U11  TPS254900-Q1  [RVC20]  149.48 121.91 0 top
U12  TPD1E10B09  [DPY]  18.41 120.51 270 top
U13  24WC256  [SO8-25X75-295]  127 118.86 180 top
U14  TPA6304-Q1  [DDV44]  178.69 117.46 0 top
U15  TPD1E10B09  [DPY]  18.41 117.34 90 top
U16  TUSB4020BI-Q1  [PHP48-12X70]  106.43 116.32 180 top
U17  TPD1E10B09  [DPY]  18.41 114.16 270 top
U18  TPD1E10B09  [DPY]  18.41 110.99 90 top
U19  Si47972  [QFN88-12X12]  45.47 110.35 270 top
U20  TPS659411  [VQFN56_19-68_320X320_0-9_EP6]  76.58 106.42 180 top
U21  TPD1E10B09  [DPY]  18.41 101.46 270 top
U22  SN74LVC1G125DCKR-Q1  [DCK-5]  48.01 100.07 180 top
U23  SN74LVC1G125DCKR-Q1  [DCK-5]  50.55 100.07 180 top
U24  NVMFS4C05NT1G  [DFN5_NTMFS4835N_240X200_1-1]  157.24 100.03 0 top
U25  SN74AVC8T245RHL-Q1  [RHL24-PVQFN-TI]  42.42 99.68 180 top
U26  TPD1E10B09  [DPY]  18.41 98.29 90 top
U27  TPS659413  [VQFN56_19-68_320X320_0-9_EP6]  131.44 97.4 270 top
U28  TPS22965NDSGR  [WSON8_19-68_80X80_0-8]  170.64 95.77 0 top
U29  TPD1E10B09  [DPY]  18.41 95.11 270 top
U30  TPD1E10B09  [DPY]  18.41 91.94 90 top
U31  MTFC32GAPALNA-AIT  [BGA100_1MM]  153.29 85.21 270 top
U32  TAS2505IR  [RGE24-11X28-4MM]  33.53 85.08 270 top
U33  LM5141-Q1  [RGE24-11X28-4MM]  193.29 84.19 270 top
U34  TPS7B7701-Q1  [PWP16-14X70-PAD]  7.75 80.13 180 top
U35  SN74LVC1G125DCKR-Q1  [DCK-5]  150.62 74.54 180 top
U36  TPS22965NDSGR  [WSON8_19-68_80X80_0-8]  27.94 72.63 180 top
U37  J721E_181212  [FCBGA827_31-49_950X950_2-8]  98.78 71.74 180 top
U38  74CBTLV1G125CRG4  [DCK-5]  195.96 71.24 0 top
U39  TPS72010QDRVR  [DRV6-12X30]  23.75 67.43 90 top
U40  MT53D1024M32D4DT  [WFBGA200_MT53DDS_400X570_1]  127.05 66.46 180 top
U41  TPD1E10B06DPY  [DPY]  29.59 60.57 90 top
U42  DP83TC811-Q1  [RND36-24X10]  40.77 58.54 180 top
U43  TPD1E10B06DPY  [DPY]  29.59 58.03 270 top
U44  TCAN1042HGVQ1  [SO8-25X75]  58.93 56.89 180 top
U45  SN74LVC1G08DCKR-Q1  [DCK-5]  80.26 53.46 180 top
U46  LM5176-Q1  [PWP28-14X70]  188.85 52.69 90 top
U47  74CBTLV1G125CRG4  [DCK-5]  142.88 51.17 0 top
U48  74CBTLV1G125CRG4  [DCK-5]  145.67 51.17 0 top
U49  74CBTLV1G125CRG4  [DCK-5]  148.46 51.17 0 top
U50  TCAN1043D-Q1  [SO14-25X75]  28.96 49.27 180 top
U51  SN74AVC4T245RGYR-Q1  [RGY16-12X34]  42.29 35.68 270 top
U52  FT2232H  [PQFP64PM]  27.69 32.88 0 top
U53  TPS73433  [DRV6-12X30]  16.89 32.25 180 top
U54  TPS62090  [RGT16-12X34]  156.08 30.09 270 top
U55  SN74AVC4T245RGYR-Q1  [RGY16-12X34]  42.29 28.56 270 top
U56  93AA46B  [DBV6-27X39-6]  17.53 23.99 90 top
U57  TPS61252  [DSG8-11X20]  40.77 21.33 270 top
U58  LP5912Q1.1DRVTQ1  [DRV6-12X30]  79.25 17.39 270 top
U59  LP5912Q1.1DRVTQ1  [DRV6-12X30]  120.02 14.72 90 top
U60  TPD2E001DRL-Q1  [DRL5-12X40]  16.89 12.56 0 top
U61  LMR23625CF-Q1  [DDA8-PAD]  158.5 12.56 0 top
U62  TPS1H100-Q1  [PWP14-14X70-PAD]  96.9 8.88 0 top
U63  LP5912Q3.3DRVTQ1  [DRV6-12X30]  120.02 8.37 90 top
U64  LM74700QDBVTQ1  [DBV6-27X39-6]  173.99 8.24 90 top
U65  tpd4e05u06-q1  [DQA-PSON10]  146.81 139.05 180 bottom
U66  tpd4e05u06-q1  [DQA-PSON10]  127.89 139.05 180 bottom
U67  APPLE_I2C_CHIP - NOPOP  [IC8-CP-USON]  195.83 99.43 90 bottom
U68  TPS22965NDSGR  [WSON8_19-68_80X80_0-8]  64.21 97.68 270 bottom
U69  TPD2E001DRL-Q1  [DRL5-12X40]  21.59 86.48 90 bottom
U70  TPD2E001DRL-Q1  [DRL5-12X40]  21.59 81.78 90 bottom
U71  TPD2E001DRL-Q1  [DRL5-12X40]  21.46 77.21 90 bottom
U72  TPD2E001DRL-Q1  [DRL5-12X40]  21.46 72.63 90 bottom
U73  MT35XU512ABA1G12-0AUT  [TPBGA24_39-37_240X320_1-2]  79.38 45.96 180 bottom
U74  DS90UB960Q  [RTD0064F]  64.77 26.15 0 bottom
U75  PDS90UB941ASRTDTQ1  [QFN64_19-68_360X360_0-9_EP6]  108.71 23.27 180 bottom
U76  25.000MHz  [OSC4_ASDMB_100X85_SMD_0-9]  100.19 21.25 90 bottom
U77  SN74LV1T08DBVR  [DBV-20X60-5]  149.86 68.44 0 top
U78  TPD1E10B06DPY  [DPY]  129.79 10.66 180 bottom
Y1  22.5792MHz  [XTAL4_S3225A_135X110_SMD_0-8]  74.93 73.27 0 top
Y2  32.768KHz  [XTAL_ECS-32_130X60_SMD_0-9]  74.93 69.46 0 top
Y3  25MHz/10pF  [XTAL4-ABM11]  41.78 65.65 90 top
Y4  19.200MHz  [XTAL4_ABM10W_100X80_SMD_0-6]  74.8 65.65 0 top
Y5  12MHz CRYSTAL  [XTAL4-63X50-ECX53B]  18.41 17.52 270 top
Y6  36.864MHz  [XTAL4-55X47-3225]  49.91 114.42 90 bottom
Y7  24 MHz/18pF  [XTAL2-75X94]  115.57 113.91 90 bottom
Y8  32.768KHz  [XTAL_ECS-32_130X60_SMD_0-9]  137.94 88.83 180 bottom

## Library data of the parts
C1 C51 C52 C55 C98 C99 C105 C106 C111 C114 C115 C119-C121 C124 C135-C142 C145 C151-C155 C157 C158 C166-C169 C172-C176 C179-C181 C183 C194 C197 C198 C200 C201 C211-C214 C218-C220 C229 C233 C234 C242 C246 C250 C254 C258 C269-C271 C274 C284 C285 C288 C291-C295 C297 C298 C300 C302 C304 C306 C307 C309 C324-C332 C340-C344 C346 C351 C352 C360 C362 C365 C367 C368 C370 C372 C374-C377 C379 C381 C382 C386-C389 C391-C397 C399 C406-C408 C410 C417-C422 C429 C430 C432-C435 C441 C442 C445 C446 C449 C451-C454 C493-C496 C509 C510 C519 C520 C527 C528 C535 C536 C538 C543-C550 C552-C560 C563 C564 C568-C578 C580 C582-C593 C598-C606 C610 C612 C615-C644 C649-C655 C657-C659 C662-C665 C667-C674 C677-C680 C682-C696 C698-C712 C714-C720 C722-C728 C730-C745 C747 C748 C750-C753 C755-C768 C770-C787 C789-C804 C806 C807 C809-C817 C820 C821 C824 C826 C828 C831 C832 C836 C839 = CAP
C2 C15 C16 C22 C26 C27 C29 C30 C32 C34 C38 C40 C44 C48-C50 C57 C61 C62 C66-C69 C71 C77 C79 C91 C93 C118 C127 C144 C251 C492 C746 C749 = CAP NP_3
C3 C11-C14 C19 C20 C65 C72 C110 C113 C128-C131 C235 C236 C253 C266 C272 C350 C450 C455 C458 C478 C483 C488-C491 C525 = CAP NP_0: Tolerance: X; User Part Number: X
C4 C5 C28 C45 C46 C431 C440 C457 C459 C464 C472 = CAP_AM_0805_4.7uf_x7r_16v_10_X: Tolerance: X; User Part Number: X
C6-C9 C17 C24 C35 C42 C54 C64 C80 C96 C102 C109 C147 C161 C177 C199 C223 C225 C226 C239 C249 C308 C320 C321 C348 C357 C484-C487 C499 C660 C681 = CAP NP
C10 C63 C78 C112 C143 C202 C313 C465 C469-C471 C473-C476 C788 C805 C808 C818 C819 C822 C823 C825 C827 C829 C830 C834 C835 = CAP: User Part Number: USERPART#; Tolerance: TOLERANCE
C18 C23 C25 C31 C36 C53 C81 C95 C103 C108 C148 C160 C178 C195 = CAP NP_3: Tolerance: X; User Part Number: X
C21 C41 C60 C70 C73-C76 C263 C311 C319 C333 C353 C361 C477 C500-C505 C517 C518 C769 C837 C838 = CAP NP: Tolerance: X; User Part Number: X
C33 C37 C58 C59 C82 C97 C100 C104 C122 C123 C149 C156 C159 C162-C165 C182 C184 C187 C188 C191-C193 C196 C203 C227 C228 C244 C245 C252 C256 C257 C259 C283 C289 C296 C299 C301 C303 C345 C347 C355 C356 C363 C366 C369 C371 C373 C378 C380 C384 C390 C398 C400 C403-C405 C415 C416 C438 C439 C443 C444 C447 C448 C456 C460-C463 C467 C479-C482 C565 C579 C581 C597 C609 C613 C666 C675 C676 C697 C833 = CAP: Tolerance: X; User Part Number: X
C39 C354 C468 C522 C551 C561 C562 C566 C567 = CAP_AM_0402_0.1uf_x7r_16v_10%_X
C43 C310 C358 C364 C436 C437 C513 C514 C529 C530 C645-C648 C713 C754 = CAP NP_0: User Part Number: X; Tolerance: X
C47 = CAP_AM_0402_0.1uf_x7r_16v_10%_X: Tolerance: X; User Part Number: X
C56 = CAP_AM_0402_0.1uf_x7r_16v_10%_X: User Part Number: USERPART#; Tolerance: TOLERANCE
C83 C84 C92 C116 C125 C150 = CAP_AM_0603_1.0uf_x7r_16v_10_X
C85 C86 C117 C126 C146 = CAP_AM_0603_2.2uf_x7r_6.3v_10_X
C87 C89 C132 C134 C383 C409 C423 C424 = CAP_AM_0805_10uf_x7r_10v_10_X: Tolerance: X; User Part Number: X
C88 C133 = CAP_0402_0.1uf_x7r_16v_10%_X_SD: User Part Number: USERPART#; Tolerance: +/-10%; tolerance: +/-10%
C90 C94 C209 C237 C238 C240 C260 C261 C273 C281 C286 C385 C497 C594 C596 = Cap 100nF Cermc 16V 10% 603_4
C101 C107 = CAP NP_3: Tolerance: TOLERANCE; User Part Number: USERPART#
C170 C185 C186 C204-C208 C215-C217 C221 C222 C231 C247 C264 C267 C268 C275-C277 C282 C287 C290 C317 C318 C322 C323 C334 C335 C337-C339 C359 C595 C614 = CAP_NFM
C171 C189 C190 C210 C232 C241 C248 C255 C265 C314 C336 C349 = CAP_NFM: User Part Number: PART#; Tolerance: TOL
C224 C243 C262 C607 = CAP NP_2
C230 = CAP NP_2: Tolerance: X; User Part Number: X
C278-C280 = CAP NP_0: User Part Number: X; Tolerance: 20%; tolerance: 20%
C305 = CAP: User Part Number: X; Tolerance: X
C312 C316 = CAP NP: Tolerance: X; User Part Number: X; signal model: CAP_NP_C603-35X45_0.1UF_0.1uF
C315 = CAP_0402_220pf_x7r_50v_10%_X_SD: tolerance: +/-10%
C401 C402 C411-C414 C425-C428 = CAP: signal model: CAP_C201-6P6SPC_0.22UF_0.22uF
C466 = CAP_AM_0603_0.47uf_x7r_16v_10_X: Tolerance: X; User Part Number: X
C498 = CAP NP_0
C506-C508 C511 C512 C515 C516 C523 C524 C526 C531-C534 = CAP: Tolerance: TOLERANCE; User Part Number: USERPART#
C521 = CAP .1 uF 10% 0603
C537 C539-C542 = CAP_AM_0402_0.01uf_x7r_25v_10_X: User Part Number: USERPART#; Tolerance: TOLERANCE
C608 C611 = Cap 100nF Cermc 16V 10% 603_4: Tolerance: X; User Part Number: X
D1 D14 DS1 = LED_RED_0: Tolerance: X; User Part Number: X
D2 D3 D5 = DIODE BI-DIR TRIG_0: Tolerance: X; User Part Number: X
D4 = DIODE_ZENER_SOT23_13
D6 = DIODE_ZENER
D7 = DIODE SCHOTTKY_0: User Part Number: X; Tolerance: X
D8 D9 D13 = DIODE SCHOTTKY_0: Tolerance: TOLERANCE; User Part Number: USERPART#
D10 = DIODE ZENER: Tolerance: TOLERANCE; User Part Number: USERPART#
D11 D12 = DIODE
D15-D24 = DIODE_TPD1E05U06: Tolerance: X; User Part Number: X
D25 D26 = Diode_SMCJ15CA
FL1 = DLW21SN121HQ2: User Part Number: PART#; Tolerance: TOL
FL2 FL3 = DLW21SN121HQ2: User Part Number: PART#; Tolerance: TOL; signal model: DLW21SN121HQ2_EMI-36X15-DLW21_D_DLW21SN121HQ2
FL4 FL5 FL12-FL14 FL16 FL20-FL25 FL27 FL32-FL34 = EMIFILTER_IND
FL6-FL11 FL15 FL17-FL19 FL39 = EMIFILTER_IND: Tolerance: X; User Part Number: X
FL26 FL28-FL31 FL35-FL38 FL41 = DLW21SN121HQ2: User Part Number: PART#; Tolerance: TOL; signal model: DLW21SN121HQ2_EMI-36X15-DLW21-R_DLW21SN900HQ2
FL40 = CAP_FILTER: Tolerance: TOL; User Part Number: PART#
HS1 = HS-DDV44: Tolerance: TOLERANCE; User Part Number: USERPART#
J1 J2 = 1932258-1-USB3
J3 = CONN TRBLK 8_0: User Part Number: X; Tolerance: X
J4 = CONN TRBLK 2_0
J5-J7 P1-P4 = 59S20X-400L5-Z: Tolerance: TOLERANCE; User Part Number: USERPART#
J8 J9 J12 = CON_AUDIOJACK6_STX-4235-3/3
J10 = HEADER 3: Tolerance: TOL; User Part Number: PART#
J11 = HEADER 5X2: Tolerance: X; User Part Number: X
J13 = Molex34826-0124: Tolerance: TOLERANCE; User Part Number: USERPART#
J14 = HEADER 2
J15 = MIPI-QTH-030_1: User Part Number: PART#; Tolerance: TOL
J16 = CON_JACK4_EXG.0B.304
J17 = Phoenix_1868076
J18 = CON20_USB_F_TI
J19 = USBMINI_B_0
J20 = mini-pcie
J21 = FX8-120P-SV1-91
L1 L2 = INDUCTOR: User Part Number: USERPART#; Tolerance: TOLERANCE
L3 L5-L7 L12 L14-L18 L20-L26 L47 L48 = INDUCTOR: Tolerance: X; User Part Number: X
L4 L8-L11 L55-L58 = INDUCTOR IRON: Tolerance: TOLERANCE; User Part Number: USERPART#
L13 L19 = INDUCTOR: User Part Number: X; Tolerance: X
L27 L31 L51-L54 L59-L66 L71-L74 = FERRITE CHIP_0: Tolerance: X; User Part Number: X
L28-L30 L32-L38 = INDUCTOR
L39 L43 = INDUCTOR IRON
L40 L42 = CHOKE HASH-IRON: Tolerance: X; User Part Number: X; signal model: CHOKE_HASH-IRON_L603-35X45_120N_120nH
L41 = CHOKE CM_AE2002: User Part Number: USERPART#; Tolerance: TOLERANCE
L44 L50 = INDUCTOR IRON: User Part Number: X; Tolerance: X
L45 = INDUCTOR IRON: Tolerance: X; User Part Number: X
L46 = CHOKE HASH-IRON: User Part Number: USERPART#; Tolerance: TOLERANCE
L49 = CHOKE HASH-IRON
L67-L70 = CHOKE: User Part Number: USERPART#; Tolerance: TOLERANCE
L75-L78 = CHOKE: Tolerance: TOLERANCE; User Part Number: USERPART#
M1-M4 M7 M8 = MHP125-250
M5 M6 = NT1R3000
P5 = molex-502774-0891: User Part Number: X; Tolerance: X
PL1 = PL0201: User Part Number: USERPART#; Tolerance: TOLERANCE
Q1 Q2 Q8 Q15 = BSS138PS: User Part Number: X; Tolerance: X
Q3-Q5 Q7 Q10-Q13 = BSZ042N06NS: User Part Number: X; Tolerance: X
Q6 = MOSFET N_1: Tolerance: X; User Part Number: X
Q9 = MOSFET_CSD16406Q3_0: User Part Number: X; Tolerance: X
R1-R11 R13-R16 R20 R22-R27 R33 R37 R39-R48 R52-R54 R56-R58 R65-R70 R75-R80 R95-R97 R101-R103 R106-R108 R111 R113 R114 R117 R123-R125 R129 R133 R137-R140 R148 R152 R154 R156 R157 R162 R164 R165 R171 R176-R179 R210 R212 R215 R217 R219 R222-R226 R229 R230 R232 R234-R239 R243-R245 R247 R254-R256 R258 R262-R270 R272 R280 R281 R287 R292 R295 R296 R307 R308 R313 R315 R323 R342 R354 R355 R357 R362-R364 R367-R372 R375-R377 R379 R380 R382 R386 R388-R394 R403 R405-R408 R410-R415 R424 R425 R432 R439 R450 R452-R454 R459-R462 = R
R12 R38 R49-R51 R55 R127 R150 R159-R161 R167 R168 R170 R172 R173 R182 R184 R189 R193 R198 R199 R202 R251 R253 R260 R271 R299 R300 R309 R310 R326 R327 R438 = R_2
R17-R19 R21 R28-R32 R64 R71 R72 R74 R83 R84 R98 R99 R105 R132 R135 R141-R147 R149 R151 R174 R183 R185 R186 R190 R192 R196 R200 R201 R203-R208 R240 R241 R246 R248 R249 R257 R259 R261 R277 R283-R286 R289-R291 R294 R297 R298 R301 R303-R306 R311 R312 R314 R318 R321 R324 R325 R328-R330 R337 R338 R343 R349 R352 R353 R358 R359 R361 R365 R366 R381 R426-R431 R433-R437 R440 R442 R443 R445-R448 R455-R458 R463-R465 = RESISTOR
R34 R36 R273-R276 R278 R279 = R_2: User Part Number: USERPART#; Tolerance: TOLERANCE
R35 R60 R62 R63 R73 R112 R118 R121 R126 R131 R136 R163 R166 R169 R187 R188 R194 R195 R211 R213 R228 R233 R242 R282 R288 R316 R319 R320 R331-R334 R336 R339 R341 R345 R346 R348 R351 R356 R360 R373 R374 R385 = RESISTOR: User Part Number: USERPART#; Tolerance: TOLERANCE
R59 R100 R115 R128 R191 R209 R220 = R: User Part Number: USERPART#; Tolerance: TOLERANCE
R61 R250 = R_1
R81 R82 R85-R94 R110 = R_1: User Part Number: USERPART#; Tolerance: TOLERANCE; signal model: R_1_R201-18P5X15_44.2_44.2
R104 R180 = R_2: Tolerance: X; User Part Number: X
R109 R116 R120 R122 R130 R134 R395-R402 R416-R423 = R_1: User Part Number: USERPART#; Tolerance: TOLERANCE
R119 R197 R302 = RESISTOR: signal model: RESISTOR_R402-25_22E_22E
R153 R175 R181 R252 = R_2: User Part Number: X; Tolerance: X
R155 R158 R214 R216 R218 R221 R227 R231 R441 R444 R449 R451 = R_0
R293 = RES_0402_10k_1.0%_0.063W_X: tolerance: 1.0%
R317 = RESISTOR: signal model: RESISTOR_R402-25_0_0
R322 R335 R340 R344 R347 R350 = RESISTOR: User Part Number: USERPART#; Tolerance: TOLERANCE; signal model: RESISTOR_R201-18P5X15_36_36
R378 = RESISTOR: signal model: RESISTOR_R402-25_22E_22Ea
R383 = RESISTOR: signal model: RESISTOR_R402-25_22_22
R384 R387 R404 R409 = R: Tolerance: X; User Part Number: X
RJ1 RJ3-RJ16 RJ18-RJ20 = RJUMP3: Tolerance: TOLERANCE; User Part Number: USERPART#
RJ2 = RJUMP3A: Tolerance: TOLERANCE; User Part Number: USERPART#
RJ17 = RJUMP3B: Tolerance: TOLERANCE; User Part Number: USERPART#
SW1 = SW DIP-2_0: User Part Number: X; Tolerance: X
SW2 = SW DIP-8: User Part Number: X; Tolerance: X
SW3 = SW PUSHBUTTON_3: User Part Number: X; Tolerance: X
TP1 TP36 TP37 TP69 = TESTPOINT: User Part Number: USERPART#; Tolerance: TOLERANCE
TP2-TP5 TP7-TP9 TP12 TP15 TP18 TP33 TP41 TP42 TP44 TP45 TP53 TP60-TP65 TP67 TP68 TP70 TP72-TP74 = TP-30RD13: Tolerance: TOLERANCE; User Part Number: USERPART#
TP6 TP20-TP22 TP24-TP31 TP43 TP46-TP48 TP58 TP59 TP71 = TP-20RD10
TP10 TP11 TP56 = TESTPOINT: Tolerance: TOLERANCE; User Part Number: USERPART#
TP13 TP14 TP16 TP17 TP19 TP23 TP32 TP34 TP35 TP38 TP40 TP49-TP51 TP54 TP55 TP66 TP76 TP77 = TP_VIA_MEM0_0: User Part Number: USERPART#; Tolerance: TOLERANCE
TP39 TP57 TP75 = TESTPOINT
TP52 TP78-TP84 = SMT-TP
U1 = U-TPS78601_AJUST - 1_3.5A LDO: Tolerance: X; User Part Number: X
U2 = NEO-M8U: Tolerance: X; User Part Number: X
U3-U5 U9 U12 U15 U17 U18 U21 U26 U29 U30 U41 U43 U78 = TPD1E10B09: Tolerance: X; User Part Number: X
U6 U58 U59 U63 = LP5912-Q1: User Part Number: X; Tolerance: X
U7 = TPD3S716-Q1: User Part Number: USERPART#; Tolerance: TOLERANCE
U8 = LM53603-Q1: Tolerance: X; User Part Number: X
U10 U45 = SN74LVC1G08DBVRE4_SOT23-5: User Part Number: PART#
U11 = TPS254900-Q1
U13 = 24WC256: User Part Number: X; Tolerance: X
U14 = TPA6304-Q1
U16 = TUSB4020BI-Q1
U19 = Si47972
U20 U27 = TPS65941-Q1_VQFN56_0
U22 U23 = SN74LVC1G125_0: User Part Number: PART#; signal model: SN74LVC1G125_0_DCK-5_SN74LVC1G1_SN74LVC1G125DCKR-Q1
U24 = MOSFET-SIS434DN
U25 = SN74AVC8T245_1
U28 U36 U68 = TPS22965DSGT_WSON8_0
U31 = MTFC32GAKAEDQ-AIT: Tolerance: TOL; User Part Number: PART#
U32 = TAS2505IR
U33 = LM5141-Q1
U34 = TPS7B7701-Q1: Tolerance: X; User Part Number: X
U35 U38 U47-U49 = SN74LVC1G125_0: User Part Number: PART#
U37 = J7ES-EVM_BGA827_0
U39 = TPS72010QDRVR: User Part Number: X; Tolerance: X
U40 = MT53D1024M32D4DT_VFBGA200
U42 = DP83TC811-Q1
U44 = SN65HVDA541: Tolerance: X; User Part Number: X
U46 = LM5175-Q1: Tolerance: X; User Part Number: X
U50 = TCAN1043D-Q1: Tolerance: X; User Part Number: X
U51 U55 = SN74AVC4T245RGYR_0: Tolerance: X; User Part Number: X
U52 = FT2232H_0
U53 = TPS73433_1: User Part Number: X; Tolerance: X
U54 = TPS62090: User Part Number: X; Tolerance: X
U56 = 93C46_3V3: User Part Number: X; Tolerance: X
U57 = TPS61252: User Part Number: X; Tolerance: X
U60 = TPD2E001_0
U61 = LMR23625CF-Q1: Tolerance: X; User Part Number: X
U62 = tps1h100-q1: Tolerance: X; User Part Number: X
U64 = LM74700QDBVTQ1: User Part Number: X; Tolerance: X
U65 U66 = tpd4e05u06-q1: Tolerance: TOL; User Part Number: PART#
U67 = APPLE_I2C_CHIP: User Part Number: X; Tolerance: X
U69-U72 = TPDE0001RSE_0
U73 = MT35XU512ABA1G12_TPBGA24_0
U74 = DS90UB960Q
U75 = DS90UB941AS-Q1_VQFN64
U76 = OSC4_ASDMB
U77 = SN74LVC1G08DCK: User Part Number: X; Tolerance: X
Y1 Y4 = CRY4_ABM8G
